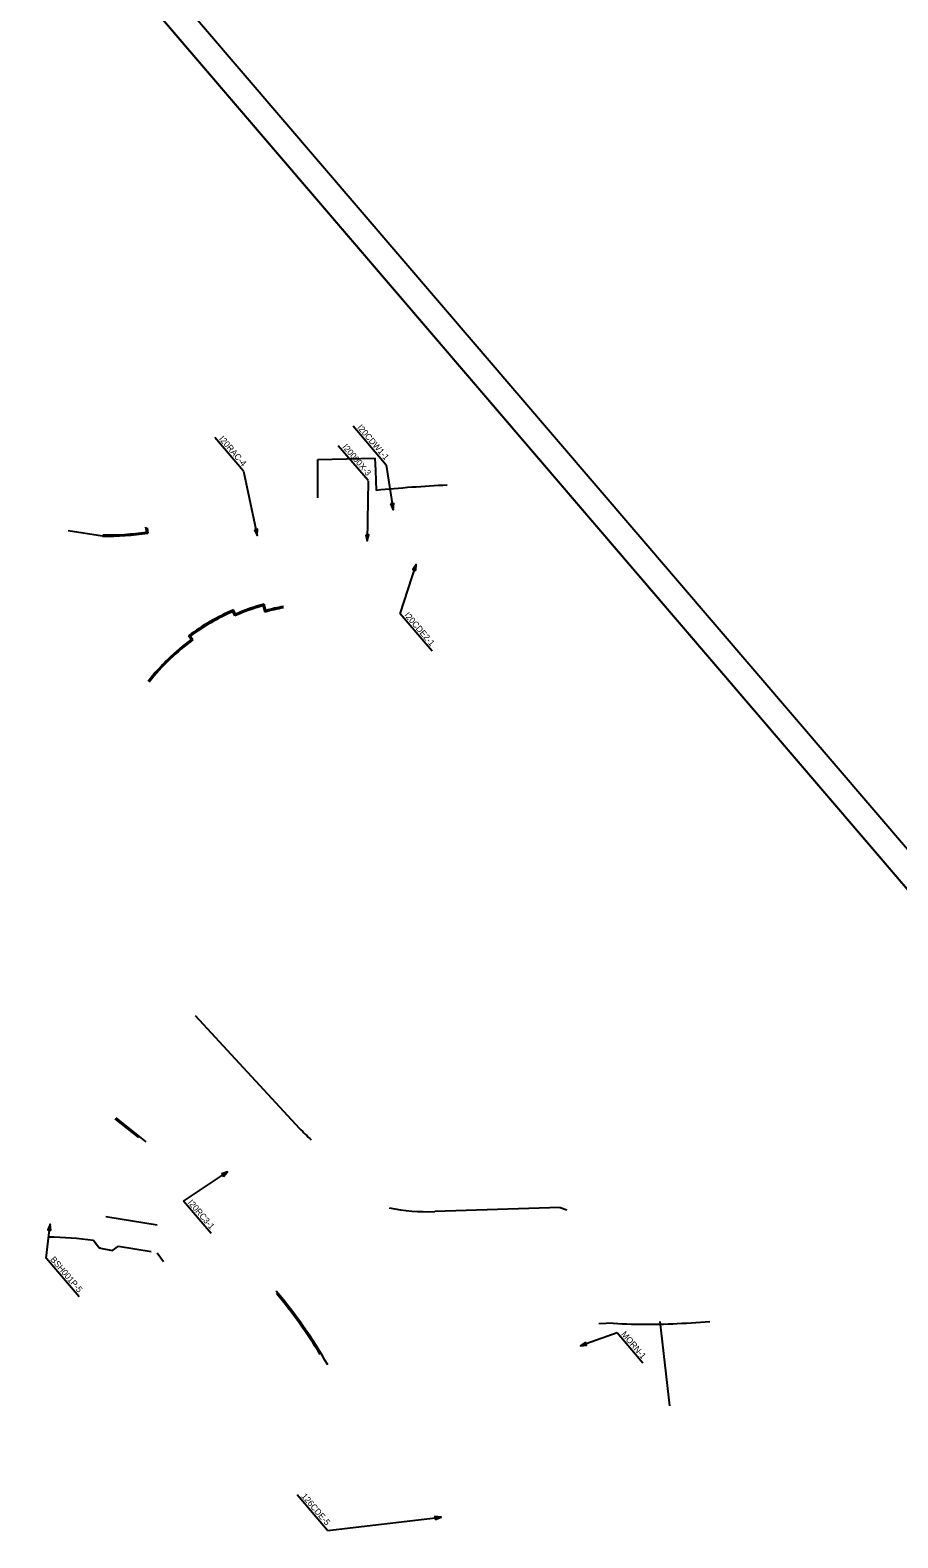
# Model space of a CAD drawing. Extents: x 1941897 to 1978064, y 805467 to 836604.
# Drawn here: x 1956688 to 1960037, y 817410 to 823229 of the extents above; entities that cross this region are included whole.
import ezdxf

# ---------------------------------------------------------------- set-up
doc = ezdxf.new("R2010")
doc.units = 0
for name, color, linetype in [('RD_EX_DV_Prop', 7, 'Continuous'), ('RD_EX_H20_TX', 7, 'Continuous'), ('RD_PD_Control_Access', 7, 'Continuous'), ('RD_PD_RW', 7, 'Continuous'), ('RD_SHT_Bndy', 7, 'Continuous'), ('RD_SHT_IplotShp', 7, 'Continuous'), ('RD_TX_RoadID', 7, 'Continuous')]:
    doc.layers.add(name, color=color, linetype=linetype)

msp = doc.modelspace()

# ---------------------------------------------------------------- linework, layer by layer
at = {"layer": 'RD_EX_DV_Prop'}
msp.add_line((1959156.5, 817919.5), (1959119.6, 818245.5), dxfattribs=at)
at = {"layer": 'RD_EX_H20_TX'}
for points in [[(1963151.2, 810860.3), (1959509.3, 815114.3), (1958096.8, 813905.1), (1957040.5, 814307.7), (1947588.1, 825348.6), (1952108, 829218.2), (1965848, 813169.1)], [(1963151.2, 810860.3), (1959509.3, 815114.3), (1958096.8, 813905.1), (1957040.5, 814307.7), (1947588.1, 825348.6), (1952108, 829218.2), (1965848, 813169.1)], [(1963151.2, 810860.3), (1959509.3, 815114.3), (1958096.8, 813905.1), (1957040.5, 814307.7), (1947588.1, 825348.6), (1952108, 829218.2), (1965848, 813169.1)], [(1963151.2, 810860.3), (1959509.3, 815114.3), (1958096.8, 813905.1), (1957040.5, 814307.7), (1949323.3, 823321.8), (1953668.8, 827395), (1965848, 813169.1)], [(1963151.2, 810860.3), (1959509.3, 815114.3), (1958096.8, 813905.1), (1957040.5, 814307.7), (1949323.3, 823321.8), (1953668.8, 827395), (1965848, 813169.1)], [(1963151.2, 810860.3), (1959509.3, 815114.3), (1958096.8, 813905.1), (1957040.5, 814307.7), (1949323.3, 823321.8), (1953668.8, 827395), (1965848, 813169.1)]]:
    msp.add_lwpolyline(points, close=True, dxfattribs=at)
at = {"layer": 'RD_PD_Control_Access'}
for p, q in [((1956967.5, 821276.2), (1956834.3, 821296.5)), ((1957139.2, 821307.6), (1957142.2, 821287.8)), ((1957480.1, 820975), (1957472.9, 820991.5)), ((1957597.8, 820989), (1957590.8, 821014)), ((1957309.2, 820876.9), (1957298.5, 820891.4)), ((1957018.1, 819031.1), (1957135, 818938.9))]:
    msp.add_line(p, q, dxfattribs=at)
for centre, radius, start, end in [((1956991.6, 822230.9), 955, 268.5568, 279.07384), ((1957820.2, 820185.1), 878, 113.2985, 126.44821), ((1957820.2, 820185.1), 860, 105.47088, 113.29167), ((1957820.2, 820185.1), 834, 100.69815, 105.46049), ((1957820.2, 820185.1), 860, 126.45504, 141.90894), ((1956182.7, 817132.2), 1905, 29.75294, 40.20711)]:
    msp.add_arc(centre, radius, start, end, dxfattribs=at)
at = {"layer": 'RD_PD_RW'}
for p, q in [((1957797.8, 821424.3), (1957798.4, 821571.3)), ((1957798.4, 821571.3), (1958019.8, 821577.3)), ((1958021.5, 821529.9), (1958019.8, 821577.3)), ((1958024.3, 821452.4), (1958021.5, 821529.9)), ((1957133.5, 821311.8), (1957136.5, 821292)), ((1957477.5, 820968.5), (1957470.3, 820985)), ((1957594.4, 820982.8), (1957587.3, 821007.8)), ((1957316.1, 820875.8), (1957305.5, 820890.3)), ((1957325.1, 819425.7), (1957727.8, 818990.5)), ((1957015.1, 819027.1), (1957106.4, 818955)), ((1956980.1, 818650.8), (1957177.7, 818617.6)), ((1958733.8, 818685.4), (1958249.2, 818669.3)), ((1958733.8, 818685.4), (1958758.9, 818676.3)), ((1956954.2, 818528.4), (1956932.2, 818557)), ((1957006.2, 818519.6), (1957028.8, 818536.1)), ((1957028.8, 818536.1), (1957154.7, 818515)), ((1956959.4, 818527.5), (1957006.2, 818519.6)), ((1957177.6, 818510.4), (1957202.6, 818476.5)), ((1959221, 818239), (1959311.8, 818244.4)), ((1958937.9, 818238.2), (1958882.4, 818236.5))]:
    msp.add_line(p, q, dxfattribs=at)
for centre, radius, start, end in [((1958539.3, 816378.4), 5100.1, 92.7116, 95.7959), ((1956991.6, 822230.9), 950, 268.57581, 278.77386), ((1957820.2, 820185.1), 873, 113.62479, 126.12193), ((1957820.2, 820185.1), 855, 105.80399, 113.62479), ((1957820.2, 820185.1), 829, 100.69815, 105.80399), ((1957820.2, 820185.1), 855, 126.12193, 141.90894), ((1958223.3, 819448.9), 675, 222.77633, 228.14366), ((1958223.3, 819448.9), 780, 258.90146, 271.90428), ((1956740.2, 817220.8), 1350, 81.82507, 89.20714), ((1956740.2, 817220.8), 1325, 80.47781, 80.70607), ((1956182.7, 817132.2), 1900, 31.23339, 39.97666), ((1959073.3, 820682.5), 2448, 266.82922, 273.46093)]:
    msp.add_arc(centre, radius, start, end, dxfattribs=at)
at = {"layer": 'RD_SHT_Bndy'}
msp.add_lwpolyline([(1960707.9, 808409.5), (1943668.8, 828312), (1948986.3, 832864.4), (1966025.3, 812961.9)], close=True, dxfattribs=at)
at = {"layer": 'RD_SHT_IplotShp'}
msp.add_lwpolyline([(1960696.9, 808268.5), (1943527.9, 828323), (1948997.3, 833005.4), (1966166.3, 812950.9)], close=True, dxfattribs=at)
at = {"layer": 'RD_TX_RoadID'}
for p, q in [((1958062.5, 821550.5), (1957934.2, 821700.4)), ((1957511.6, 821527.3), (1957400.8, 821656.6)), ((1957992.4, 821490.5), (1957877, 821625.2)), ((1958239.4, 820832.2), (1958116.1, 820976.2)), ((1957387, 818584.3), (1957280.4, 818708.9)), ((1956876.9, 818340.5), (1956749.7, 818489.2)), ((1959053.2, 818083.7), (1958952.9, 818200.9)), ((1957835.6, 817439), (1957718.5, 817575.8))]:
    msp.add_line(p, q, dxfattribs=at)
for points in [[(1957511.6, 821527.3), (1957564.7, 821278.5)], [(1958062.5, 821550.5), (1958088.6, 821378.2)], [(1957992.3, 821489.9), (1957989, 821257.9)], [(1958116.1, 820976.2), (1958177.7, 821166.8)], [(1957280.4, 818708.9), (1957450.2, 818822.5)], [(1956749.7, 818489.2), (1956764.6, 818620.5)], [(1958952.9, 818200.9), (1958811.4, 818151.4)], [(1957835.6, 817439), (1958274.1, 817489.4)]]:
    msp.add_lwpolyline(points, dxfattribs=at)
for points in [[(1958079, 821400.2), (1958088.6, 821378.2), (1958091.2, 821402)], [(1957553.8, 821299.9), (1957564.7, 821278.5), (1957565.9, 821302.5)], [(1957983.1, 821281.2), (1957989, 821257.9), (1957995.6, 821281)], [(1958176.5, 821142.9), (1958177.7, 821166.8), (1958164.7, 821146.7)], [(1957434.3, 818804.5), (1957450.2, 818822.5), (1957427.4, 818814.8)], [(1956768.2, 818596.8), (1956764.6, 818620.5), (1956755.8, 818598.2)], [(1958831.3, 818164.9), (1958811.4, 818151.4), (1958835.4, 818153.1)], [(1958251.7, 817480.6), (1958274.1, 817489.4), (1958250.3, 817493)]]:
    msp.add_lwpolyline(points, close=True, dxfattribs=at)

# ---------------------------------------------------------------- texts
for s, p in [('I20CDW1-1', (1957948.6, 821694.3)), ('I20RAC-4', (1957415.2, 821650.5)), ('I20000X-3', (1957891.5, 821619.1)), ('I20CDE2-1', (1958130.5, 820970.1)), ('I20RC3-1', (1957294.8, 818702.8)), ('BSH001P-5', (1956764.1, 818483.1)), ('MORN-1', (1958967.3, 818194.8)), ('126CDE-5', (1957732.9, 817569.7))]:
    msp.add_text(s, height=24, rotation=310.56753, dxfattribs=at).set_placement(p)

doc.saveas('drawing.dxf')
